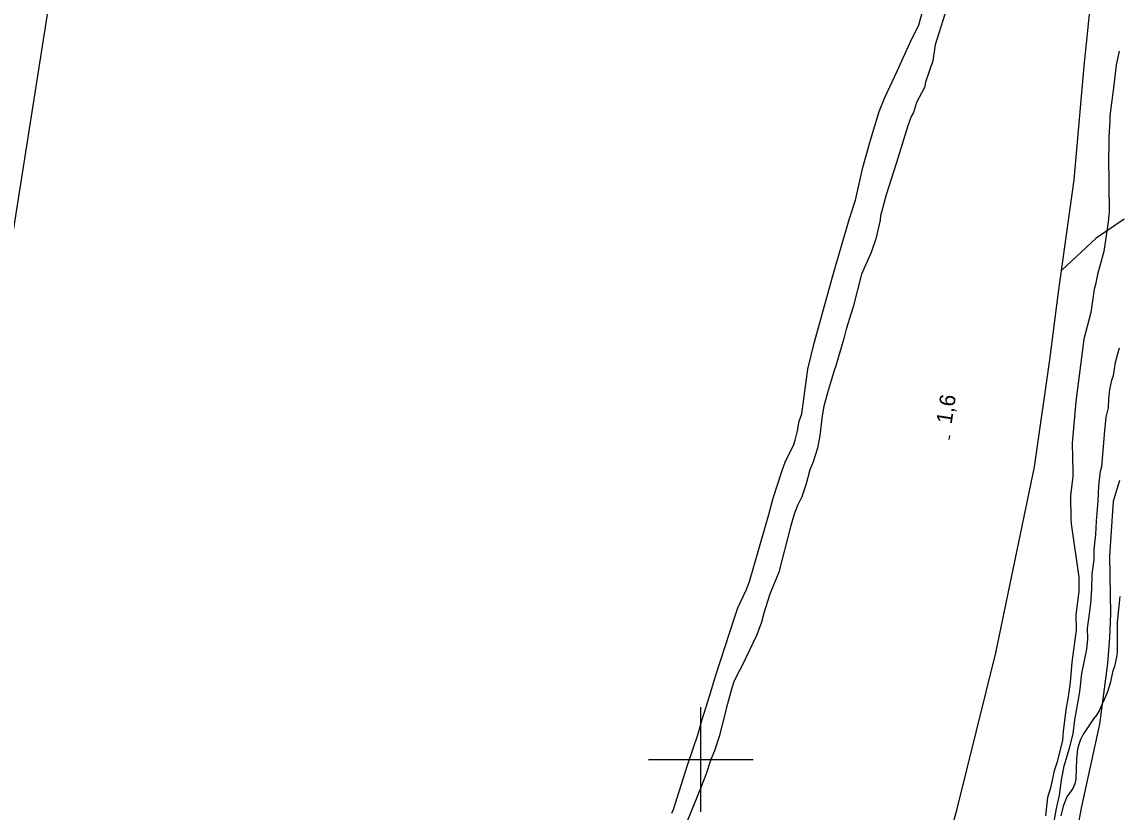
# Model space of a CAD drawing. Extents: x 282461 to 284471, y 5554090 to 5557646.
# Drawn here: x 282670.3 to 282879.7, y 5555389.9 to 5555540.9 of the extents above; entities that cross this region are included whole.
import ezdxf

# ---------------------------------------------------------------- set-up
doc = ezdxf.new("R2010")
doc.units = 0
for name, color, linetype in [('Niveau 2', 7, 'Continuous'), ('Niveau 22', 7, 'Continuous'), ('Niveau 3', 7, 'Continuous'), ('Niveau 4', 7, 'Continuous'), ('Niveau 60', 7, 'Continuous'), ('Niveau 61', 7, 'Continuous')]:
    doc.layers.add(name, color=color, linetype=linetype)

msp = doc.modelspace()

# ---------------------------------------------------------------- linework, layer by layer
at = {"layer": 'Niveau 2'}
for points in [[(282846.65, 5555542.39), (282844.8, 5555536.49), (282844.31, 5555533.48), (282842.97, 5555529.37), (282842.76, 5555528.39), (282841.23, 5555525.47), (282840.62, 5555523.61), (282840.22, 5555522.79), (282839.55, 5555521.04), (282837.43, 5555514.05), (282835.42, 5555507.87), (282834.37, 5555503.86), (282834.27, 5555503.04), (282833.44, 5555499.43), (282832.55, 5555496.81), (282830.74, 5555492.67), (282829.14, 5555486.44), (282827.75, 5555482.19), (282827.31, 5555480.39), (282825.81, 5555475.2), (282825.47, 5555474.33), (282824.19, 5555470.02), (282823.53, 5555467.46), (282823.2, 5555465.66), (282822.73, 5555461.88), (282822.29, 5555459.49), (282821.46, 5555456.82), (282820.84, 5555455.3), (282820.12, 5555452.62), (282819.28, 5555450.18), (282818.49, 5555448.54), (282817.87, 5555446.85), (282817.15, 5555444.41), (282814.94, 5555435.79), (282813.2, 5555431.54), (282812.03, 5555427.93), (282811.58, 5555426.24), (282810.69, 5555423.79), (282807.87, 5555417.84), (282806.96, 5555416.15), (282806.34, 5555414.81), (282805.84, 5555413.41), (282805.12, 5555410.62), (282804.89, 5555409.98), (282804.73, 5555409.1), (282803.52, 5555404.39), (282802.62, 5555401.66), (282801.89, 5555399.96), (282801, 5555397.23), (282800.1, 5555394.78), (282797.24, 5555387.9)], [(282879.96, 5555535.31), (282879.35, 5555532.66), (282878.93, 5555528.79), (282878.15, 5555522.92), (282878.16, 5555521.93), (282877.96, 5555519.03), (282877.99, 5555517.06), (282877.9, 5555515.14), (282878.03, 5555504.64), (282877.82, 5555502.73), (282877.02, 5555497.03), (282875.8, 5555492.61), (282875.42, 5555490.75), (282875.14, 5555489.82), (282874.56, 5555485.35), (282873.17, 5555480.28), (282871.64, 5555468.38), (282870.99, 5555460.42), (282871.11, 5555454.97), (282871.07, 5555454.05), (282870.65, 5555450.39), (282870.7, 5555445.92), (282870.77, 5555444.99), (282872.23, 5555434.8), (282872.27, 5555432.08), (282871.68, 5555427.61), (282871.72, 5555424.71), (282870.93, 5555418.55), (282870.57, 5555414.72), (282870.15, 5555411.59), (282869.82, 5555409.9), (282869.24, 5555405.37), (282869.09, 5555403.63), (282868.04, 5555399.38), (282867.54, 5555397.81), (282866.82, 5555394.56), (282866.27, 5555392.75), (282865.85, 5555389.21)], [(282867.46, 5555387.8), (282867.95, 5555390.64), (282868.55, 5555393.2), (282868.92, 5555396.04), (282869.41, 5555398.77), (282870.47, 5555402.14), (282871.13, 5555404.87), (282871.5, 5555407.54), (282872.42, 5555412.89), (282872.84, 5555416.42), (282873.76, 5555421.07), (282873.97, 5555423.04), (282873.89, 5555425.01), (282874.31, 5555427.8), (282874.52, 5555429.77), (282874.72, 5555432.61), (282874.8, 5555435.39), (282875.17, 5555438.12), (282875.15, 5555440.09), (282875.46, 5555442.99), (282875.6, 5555445.54), (282875.96, 5555449.32), (282876.04, 5555452.27), (282876.35, 5555455.06), (282876.63, 5555455.99), (282877.18, 5555462.77), (282877.49, 5555465.39), (282877.88, 5555467.19), (282877.97, 5555468.87), (282878.18, 5555470.67), (282878.56, 5555472.47), (282878.84, 5555473.34), (282879.22, 5555475.9), (282879.99, 5555478.63)], [(282880.08, 5555431.15), (282879.57, 5555426.22), (282879.58, 5555420.55), (282879.47, 5555419.56), (282879.03, 5555417.76), (282878.75, 5555416.95), (282878.21, 5555414.57), (282877.65, 5555412.71), (282876.53, 5555410.15), (282876.13, 5555409.28), (282875.62, 5555408.46), (282875.05, 5555407.76), (282873.01, 5555404.67), (282872.56, 5555403.8), (282872.22, 5555402.87), (282872, 5555401.94), (282871.79, 5555400.02), (282871.67, 5555396.2), (282871.45, 5555395.33), (282871.11, 5555394.46), (282869.97, 5555392.88), (282869.25, 5555391.08), (282868.81, 5555389.22)]]:
    msp.add_lwpolyline(points, dxfattribs=at)
at = {"layer": 'Niveau 22'}
for points in [[(282779.41, 5555163.99), (282780.99, 5555176.53), (282785.31, 5555192.12), (282790.1, 5555204.89), (282801.12, 5555231.8), (282807.25, 5555251.36), (282814.16, 5555270.05), (282820.09, 5555287.17), (282825.88, 5555305.68), (282830.88, 5555323.14), (282835.04, 5555339.71), (282840.8, 5555360.88), (282849, 5555390.56), (282856.35, 5555420.38), (282863.75, 5555455.88), (282866.69, 5555476.35), (282868.38, 5555489.24), (282871.36, 5555510.74), (282873.29, 5555532.46), (282875.51, 5555554.18), (282876.51, 5555566.61), (282878.82, 5555580.92), (282881.14, 5555589.77)], [(282880.88, 5555503.22), (282875.53, 5555499.55), (282868.97, 5555493.44)], [(282880, 5555453.31), (282878.77, 5555449.36), (282878.09, 5555438.81), (282878.3, 5555427.83), (282878.12, 5555423.32), (282877.72, 5555418.33), (282876.2, 5555406.76), (282872.76, 5555391.01), (282869.83, 5555375.47)]]:
    msp.add_lwpolyline(points, dxfattribs=at)
at = {"layer": 'Niveau 3'}
msp.add_line((282847.44, 5555461.12), (282847.56, 5555461.91), dxfattribs=at)
at = {"layer": 'Niveau 4'}
msp.add_lwpolyline([(282794.44, 5555389.75), (282794.78, 5555390.45), (282797.45, 5555398.9), (282799.52, 5555404.9), (282800.18, 5555407.46), (282801.75, 5555412.3), (282802.8, 5555415.91), (282806.49, 5555427.27), (282807.1, 5555428.96), (282808.68, 5555432.35), (282809.3, 5555433.98), (282813.02, 5555446.79), (282813.8, 5555449.88), (282815.53, 5555455.18), (282816.15, 5555456.81), (282817.78, 5555460.14), (282818.06, 5555461.02), (282818.51, 5555462.76), (282818.83, 5555464.63), (282819.28, 5555466.02), (282820.45, 5555474.57), (282821.66, 5555479.52), (282825.43, 5555493.09), (282828.43, 5555503.35), (282829.55, 5555506.85), (282830.98, 5555513.08), (282832.42, 5555518.32), (282834.09, 5555523.8), (282835.16, 5555526.43), (282837.54, 5555531.45), (282839.97, 5555536.82), (282841.66, 5555540.3), (282842.44, 5555543.08)], dxfattribs=at)
at = {"layer": 'Niveau 60'}
msp.add_lwpolyline([(282485.97, 5554340.04), (282921.22, 5557106.72), (284352.51, 5556881.56), (283917.27, 5554114.87), (282485.97, 5554340.04)], dxfattribs=at)
at = {"layer": 'Niveau 61'}
for points in [[(282800, 5555390), (282800, 5555410)], [(282790, 5555400), (282810, 5555400)]]:
    msp.add_lwpolyline(points, dxfattribs=at)

# ---------------------------------------------------------------- texts
at = {"layer": 'Niveau 3'}
msp.add_text('1,6  ', height=3, rotation=81.0957, dxfattribs=at).set_placement((282847.92, 5555463.96))

doc.saveas('drawing.dxf')
